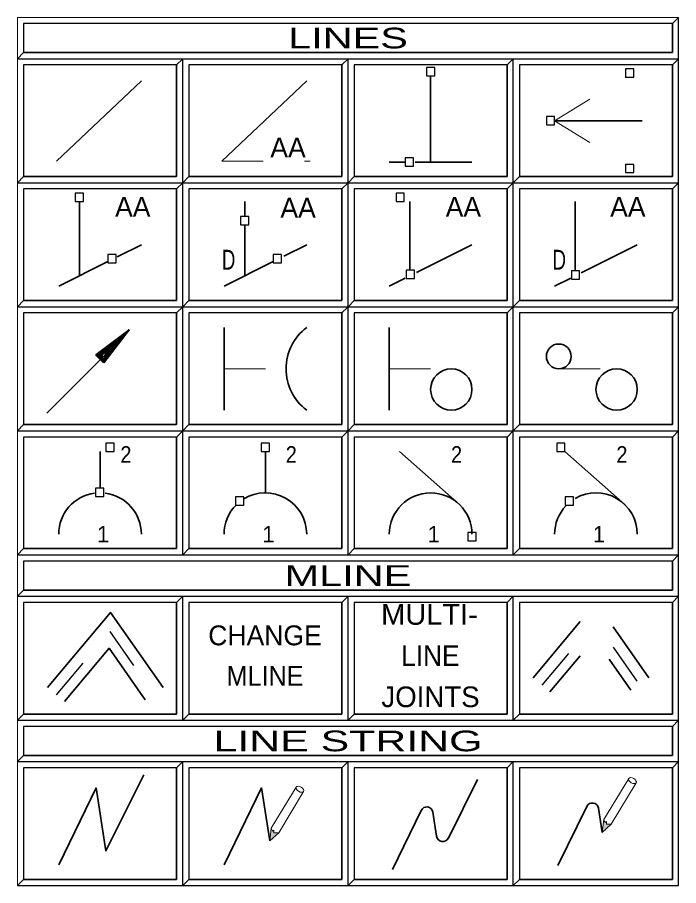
# Model space of a CAD drawing. Extents: x 95906.8 to 95923.6, y 90964.8 to 90972.8.
# Drawn here: x 95908.932 to 95910.532, y 90967.362 to 90969.462 of the extents above; entities that cross this region are included whole.
import ezdxf
from ezdxf.enums import TextEntityAlignment as Align

# ---------------------------------------------------------------- set-up
doc = ezdxf.new("R2010")
doc.units = 0
doc.header["$LTSCALE"] = 0.019
doc.linetypes.add('DOT_DASHED', pattern=[7.7, 5, -1.2, 0.3, -1.2])
doc.linetypes.add('MEDIUM_DASHED', pattern=[4.5, 3, -1.5])
for name, color, linetype, lineweight in [('11', 7, 'Continuous', 25), ('12', 7, 'Continuous', 25), ('17', 7, 'Continuous', 25), ('2', 7, 'Continuous', 13), ('3', 7, 'Continuous', 25), ('6', 7, 'Continuous', 25), ('7', 7, 'Continuous', 35)]:
    doc.layers.add(name, color=color, linetype=linetype, lineweight=lineweight)

msp = doc.modelspace()

# ---------------------------------------------------------------- hatches: boundary and pattern name
at = {"layer": '6'}
for points in [[(95910.3512, 90967.5214), (95910.3474, 90967.4906), (95910.3692, 90967.5106), (95910.3578, 90967.5102), (95910.3578, 90967.5168), (95910.3539, 90967.5142)], [(95909.5466, 90967.5005), (95909.5428, 90967.4697), (95909.5646, 90967.4897), (95909.5532, 90967.4893), (95909.5532, 90967.4959), (95909.5493, 90967.4933)]]:
    msp.add_hatch(color=256, dxfattribs=at).paths.add_polyline_path(points)

# ---------------------------------------------------------------- linework, layer by layer
at = {"layer": '11'}
for points in [[(95909.3473, 90969.0767), (95909.7173, 90969.0767), (95909.7173, 90969.3467), (95909.3473, 90969.3467)], [(95909.7473, 90969.0767), (95910.1173, 90969.0767), (95910.1173, 90969.3467), (95909.7473, 90969.3467)], [(95910.1473, 90969.0767), (95910.5173, 90969.0767), (95910.5173, 90969.3467), (95910.1473, 90969.3467)], [(95908.9473, 90968.7767), (95909.3173, 90968.7767), (95909.3173, 90969.0467), (95908.9473, 90969.0467)], [(95909.3473, 90968.7767), (95909.7173, 90968.7767), (95909.7173, 90969.0467), (95909.3473, 90969.0467)], [(95909.7473, 90968.7767), (95910.1173, 90968.7767), (95910.1173, 90969.0467), (95909.7473, 90969.0467)], [(95910.1473, 90968.7767), (95910.5173, 90968.7767), (95910.5173, 90969.0467), (95910.1473, 90969.0467)], [(95908.9473, 90968.4767), (95909.3173, 90968.4767), (95909.3173, 90968.7467), (95908.9473, 90968.7467)], [(95909.3473, 90968.4767), (95909.7173, 90968.4767), (95909.7173, 90968.7467), (95909.3473, 90968.7467)], [(95909.7473, 90968.4767), (95910.1173, 90968.4767), (95910.1173, 90968.7467), (95909.7473, 90968.7467)], [(95910.1473, 90968.4767), (95910.5173, 90968.4767), (95910.5173, 90968.7467), (95910.1473, 90968.7467)], [(95908.9473, 90968.1767), (95909.3173, 90968.1767), (95909.3173, 90968.4467), (95908.9473, 90968.4467)], [(95909.3473, 90968.1767), (95909.7173, 90968.1767), (95909.7173, 90968.4467), (95909.3473, 90968.4467)], [(95909.7473, 90968.1767), (95910.1173, 90968.1767), (95910.1173, 90968.4467), (95909.7473, 90968.4467)], [(95910.1473, 90968.1767), (95910.5173, 90968.1767), (95910.5173, 90968.4467), (95910.1473, 90968.4467)], [(95908.9473, 90967.7767), (95909.3173, 90967.7767), (95909.3173, 90968.0467), (95908.9473, 90968.0467)], [(95909.3473, 90967.7767), (95909.7173, 90967.7767), (95909.7173, 90968.0467), (95909.3473, 90968.0467)], [(95909.7473, 90967.7767), (95910.1173, 90967.7767), (95910.1173, 90968.0467), (95909.7473, 90968.0467)], [(95910.1473, 90967.7767), (95910.5173, 90967.7767), (95910.5173, 90968.0467), (95910.1473, 90968.0467)], [(95909.3473, 90967.3767), (95909.7173, 90967.3767), (95909.7173, 90967.6467), (95909.3473, 90967.6467)], [(95909.7473, 90967.3767), (95910.1173, 90967.3767), (95910.1173, 90967.6467), (95909.7473, 90967.6467)], [(95910.1473, 90967.3767), (95910.5173, 90967.3767), (95910.5173, 90967.6467), (95910.1473, 90967.6467)]]:
    msp.add_lwpolyline(points, close=True, dxfattribs=at)
at = {"layer": '12'}
for points in [[(95908.9473, 90969.0767), (95909.3173, 90969.0767), (95909.3173, 90969.3467), (95908.9473, 90969.3467)], [(95908.9473, 90967.3767), (95909.3173, 90967.3767), (95909.3173, 90967.6467), (95908.9473, 90967.6467)]]:
    msp.add_lwpolyline(points, close=True, dxfattribs=at)
at = {"layer": '17'}
for points in [[(95908.9473, 90969.3767), (95910.5173, 90969.3767), (95910.5173, 90969.4467), (95908.9473, 90969.4467)], [(95908.9473, 90968.0767), (95910.5173, 90968.0767), (95910.5173, 90968.1467), (95908.9473, 90968.1467)], [(95908.9473, 90967.6767), (95910.5173, 90967.6767), (95910.5173, 90967.7467), (95908.9473, 90967.7467)]]:
    msp.add_lwpolyline(points, close=True, dxfattribs=at)
at = {"layer": '2'}
for points in [[(95908.9323, 90969.4617), (95908.9323, 90969.3617), (95908.9473, 90969.3767), (95908.9473, 90969.4467), (95910.5173, 90969.4467), (95910.5323, 90969.4617)], [(95908.9323, 90969.3617), (95908.9323, 90969.0617), (95908.9473, 90969.0767), (95908.9473, 90969.3467), (95909.3173, 90969.3467), (95909.3323, 90969.3617)], [(95909.3323, 90969.3617), (95909.3323, 90969.0617), (95909.3473, 90969.0767), (95909.3473, 90969.3467), (95909.7173, 90969.3467), (95909.7323, 90969.3617)], [(95909.7323, 90969.3617), (95909.7323, 90969.0617), (95909.7473, 90969.0767), (95909.7473, 90969.3467), (95910.1173, 90969.3467), (95910.1323, 90969.3617)], [(95910.1323, 90969.3617), (95910.1323, 90969.0617), (95910.1473, 90969.0767), (95910.1473, 90969.3467), (95910.5173, 90969.3467), (95910.5323, 90969.3617)], [(95908.9323, 90969.0617), (95908.9323, 90968.7617), (95908.9473, 90968.7767), (95908.9473, 90969.0467), (95909.3173, 90969.0467), (95909.3323, 90969.0617)], [(95909.3323, 90969.0617), (95909.3323, 90968.7617), (95909.3473, 90968.7767), (95909.3473, 90969.0467), (95909.7173, 90969.0467), (95909.7323, 90969.0617)], [(95909.7323, 90969.0617), (95909.7323, 90968.7617), (95909.7473, 90968.7767), (95909.7473, 90969.0467), (95910.1173, 90969.0467), (95910.1323, 90969.0617)], [(95910.1323, 90969.0617), (95910.1323, 90968.7617), (95910.1473, 90968.7767), (95910.1473, 90969.0467), (95910.5173, 90969.0467), (95910.5323, 90969.0617)], [(95908.9323, 90968.7617), (95908.9323, 90968.4617), (95908.9473, 90968.4767), (95908.9473, 90968.7467), (95909.3173, 90968.7467), (95909.3323, 90968.7617)], [(95909.3323, 90968.7617), (95909.3323, 90968.4617), (95909.3473, 90968.4767), (95909.3473, 90968.7467), (95909.7173, 90968.7467), (95909.7323, 90968.7617)], [(95909.7323, 90968.7617), (95909.7323, 90968.4617), (95909.7473, 90968.4767), (95909.7473, 90968.7467), (95910.1173, 90968.7467), (95910.1323, 90968.7617)], [(95910.1323, 90968.7617), (95910.1323, 90968.4617), (95910.1473, 90968.4767), (95910.1473, 90968.7467), (95910.5173, 90968.7467), (95910.5323, 90968.7617)], [(95908.9323, 90968.4617), (95908.9323, 90968.1617), (95908.9473, 90968.1767), (95908.9473, 90968.4467), (95909.3173, 90968.4467), (95909.3323, 90968.4617)], [(95909.3323, 90968.4617), (95909.3323, 90968.1617), (95909.3473, 90968.1767), (95909.3473, 90968.4467), (95909.7173, 90968.4467), (95909.7323, 90968.4617)], [(95909.7323, 90968.4617), (95909.7323, 90968.1617), (95909.7473, 90968.1767), (95909.7473, 90968.4467), (95910.1173, 90968.4467), (95910.1323, 90968.4617)], [(95910.1323, 90968.4617), (95910.1323, 90968.1617), (95910.1473, 90968.1767), (95910.1473, 90968.4467), (95910.5173, 90968.4467), (95910.5323, 90968.4617)], [(95908.9323, 90968.1617), (95908.9323, 90968.0617), (95908.9473, 90968.0767), (95908.9473, 90968.1467), (95910.5173, 90968.1467), (95910.5323, 90968.1617)], [(95908.9323, 90968.0617), (95908.9323, 90967.7617), (95908.9473, 90967.7767), (95908.9473, 90968.0467), (95909.3173, 90968.0467), (95909.3323, 90968.0617)], [(95909.3323, 90968.0617), (95909.3323, 90967.7617), (95909.3473, 90967.7767), (95909.3473, 90968.0467), (95909.7173, 90968.0467), (95909.7323, 90968.0617)], [(95909.7323, 90968.0617), (95909.7323, 90967.7617), (95909.7473, 90967.7767), (95909.7473, 90968.0467), (95910.1173, 90968.0467), (95910.1323, 90968.0617)], [(95910.1323, 90968.0617), (95910.1323, 90967.7617), (95910.1473, 90967.7767), (95910.1473, 90968.0467), (95910.5173, 90968.0467), (95910.5323, 90968.0617)], [(95908.9323, 90967.7617), (95908.9323, 90967.6617), (95908.9473, 90967.6767), (95908.9473, 90967.7467), (95910.5173, 90967.7467), (95910.5323, 90967.7617)], [(95908.9323, 90967.6617), (95908.9323, 90967.3617), (95908.9473, 90967.3767), (95908.9473, 90967.6467), (95909.3173, 90967.6467), (95909.3323, 90967.6617)], [(95909.3323, 90967.6617), (95909.3323, 90967.3617), (95909.3473, 90967.3767), (95909.3473, 90967.6467), (95909.7173, 90967.6467), (95909.7323, 90967.6617)], [(95909.7323, 90967.6617), (95909.7323, 90967.3617), (95909.7473, 90967.3767), (95909.7473, 90967.6467), (95910.1173, 90967.6467), (95910.1323, 90967.6617)], [(95910.1323, 90967.6617), (95910.1323, 90967.3617), (95910.1473, 90967.3767), (95910.1473, 90967.6467), (95910.5173, 90967.6467), (95910.5323, 90967.6617)]]:
    msp.add_lwpolyline(points, close=True, dxfattribs=at)
at = {"layer": '3'}
for points in [[(95908.9323, 90969.3617), (95910.5323, 90969.3617), (95910.5323, 90969.4617), (95910.5173, 90969.4467), (95910.5173, 90969.3767), (95908.9473, 90969.3767)], [(95908.9323, 90969.0617), (95909.3323, 90969.0617), (95909.3323, 90969.3617), (95909.3173, 90969.3467), (95909.3173, 90969.0767), (95908.9473, 90969.0767)], [(95909.3323, 90969.0617), (95909.7323, 90969.0617), (95909.7323, 90969.3617), (95909.7173, 90969.3467), (95909.7173, 90969.0767), (95909.3473, 90969.0767)], [(95909.7323, 90969.0617), (95910.1323, 90969.0617), (95910.1323, 90969.3617), (95910.1173, 90969.3467), (95910.1173, 90969.0767), (95909.7473, 90969.0767)], [(95910.1323, 90969.0617), (95910.5323, 90969.0617), (95910.5323, 90969.3617), (95910.5173, 90969.3467), (95910.5173, 90969.0767), (95910.1473, 90969.0767)], [(95908.9323, 90968.7617), (95909.3323, 90968.7617), (95909.3323, 90969.0617), (95909.3173, 90969.0467), (95909.3173, 90968.7767), (95908.9473, 90968.7767)], [(95909.3323, 90968.7617), (95909.7323, 90968.7617), (95909.7323, 90969.0617), (95909.7173, 90969.0467), (95909.7173, 90968.7767), (95909.3473, 90968.7767)], [(95909.7323, 90968.7617), (95910.1323, 90968.7617), (95910.1323, 90969.0617), (95910.1173, 90969.0467), (95910.1173, 90968.7767), (95909.7473, 90968.7767)], [(95910.1323, 90968.7617), (95910.5323, 90968.7617), (95910.5323, 90969.0617), (95910.5173, 90969.0467), (95910.5173, 90968.7767), (95910.1473, 90968.7767)], [(95908.9323, 90968.4617), (95909.3323, 90968.4617), (95909.3323, 90968.7617), (95909.3173, 90968.7467), (95909.3173, 90968.4767), (95908.9473, 90968.4767)], [(95909.3323, 90968.4617), (95909.7323, 90968.4617), (95909.7323, 90968.7617), (95909.7173, 90968.7467), (95909.7173, 90968.4767), (95909.3473, 90968.4767)], [(95909.7323, 90968.4617), (95910.1323, 90968.4617), (95910.1323, 90968.7617), (95910.1173, 90968.7467), (95910.1173, 90968.4767), (95909.7473, 90968.4767)], [(95910.1323, 90968.4617), (95910.5323, 90968.4617), (95910.5323, 90968.7617), (95910.5173, 90968.7467), (95910.5173, 90968.4767), (95910.1473, 90968.4767)], [(95908.9323, 90968.1617), (95909.3323, 90968.1617), (95909.3323, 90968.4617), (95909.3173, 90968.4467), (95909.3173, 90968.1767), (95908.9473, 90968.1767)], [(95909.3323, 90968.1617), (95909.7323, 90968.1617), (95909.7323, 90968.4617), (95909.7173, 90968.4467), (95909.7173, 90968.1767), (95909.3473, 90968.1767)], [(95909.7323, 90968.1617), (95910.1323, 90968.1617), (95910.1323, 90968.4617), (95910.1173, 90968.4467), (95910.1173, 90968.1767), (95909.7473, 90968.1767)], [(95910.1323, 90968.1617), (95910.5323, 90968.1617), (95910.5323, 90968.4617), (95910.5173, 90968.4467), (95910.5173, 90968.1767), (95910.1473, 90968.1767)], [(95908.9323, 90968.0617), (95910.5323, 90968.0617), (95910.5323, 90968.1617), (95910.5173, 90968.1467), (95910.5173, 90968.0767), (95908.9473, 90968.0767)], [(95908.9323, 90967.7617), (95909.3323, 90967.7617), (95909.3323, 90968.0617), (95909.3173, 90968.0467), (95909.3173, 90967.7767), (95908.9473, 90967.7767)], [(95909.3323, 90967.7617), (95909.7323, 90967.7617), (95909.7323, 90968.0617), (95909.7173, 90968.0467), (95909.7173, 90967.7767), (95909.3473, 90967.7767)], [(95909.7323, 90967.7617), (95910.1323, 90967.7617), (95910.1323, 90968.0617), (95910.1173, 90968.0467), (95910.1173, 90967.7767), (95909.7473, 90967.7767)], [(95910.1323, 90967.7617), (95910.5323, 90967.7617), (95910.5323, 90968.0617), (95910.5173, 90968.0467), (95910.5173, 90967.7767), (95910.1473, 90967.7767)], [(95908.9323, 90967.6617), (95910.5323, 90967.6617), (95910.5323, 90967.7617), (95910.5173, 90967.7467), (95910.5173, 90967.6767), (95908.9473, 90967.6767)], [(95908.9323, 90967.3617), (95909.3323, 90967.3617), (95909.3323, 90967.6617), (95909.3173, 90967.6467), (95909.3173, 90967.3767), (95908.9473, 90967.3767)], [(95909.3323, 90967.3617), (95909.7323, 90967.3617), (95909.7323, 90967.6617), (95909.7173, 90967.6467), (95909.7173, 90967.3767), (95909.3473, 90967.3767)], [(95909.7323, 90967.3617), (95910.1323, 90967.3617), (95910.1323, 90967.6617), (95910.1173, 90967.6467), (95910.1173, 90967.3767), (95909.7473, 90967.3767)], [(95910.1323, 90967.3617), (95910.5323, 90967.3617), (95910.5323, 90967.6617), (95910.5173, 90967.6467), (95910.5173, 90967.3767), (95910.1473, 90967.3767)]]:
    msp.add_lwpolyline(points, close=True, dxfattribs=at)
at = {"layer": '6', "lineweight": 35}
for p, q in [((95909.9323, 90969.1117), (95909.9323, 90969.3202)), ((95909.0267, 90969.1142), (95909.2327, 90969.308)), ((95909.4267, 90969.1142), (95909.6327, 90969.308)), ((95910.2323, 90969.2117), (95910.4444, 90969.2117)), ((95909.8323, 90969.1117), (95909.8687, 90969.1117)), ((95910.0323, 90969.1117), (95909.895, 90969.1117)), ((95909.0823, 90968.8367), (95909.0823, 90969.0167)), ((95909.4823, 90969.0167), (95909.4823, 90968.9828)), ((95909.8823, 90969.0167), (95909.8823, 90968.8511)), ((95910.2823, 90969.0167), (95910.2823, 90968.8511)), ((95909.4823, 90968.8367), (95909.4823, 90968.9583)), ((95909.2323, 90968.9117), (95909.1737, 90968.8824)), ((95909.6323, 90968.9117), (95909.5772, 90968.8842)), ((95910.0323, 90968.9117), (95909.8983, 90968.8447)), ((95910.4323, 90968.9117), (95910.2966, 90968.8438)), ((95909.0323, 90968.8117), (95909.1511, 90968.8711)), ((95909.4323, 90968.8117), (95909.5509, 90968.871)), ((95909.8323, 90968.8117), (95909.8705, 90968.8308)), ((95910.2323, 90968.8117), (95910.2711, 90968.8311)), ((95909.4323, 90968.7117), (95909.4323, 90968.5117)), ((95909.8323, 90968.7117), (95909.8323, 90968.5117)), ((95909.1323, 90968.4117), (95909.1323, 90968.3255)), ((95909.5323, 90968.3117), (95909.5323, 90968.4117)), ((95910.003, 90968.2824), (95909.8573, 90968.4117)), ((95910.403, 90968.2824), (95910.2573, 90968.4117)), ((95910.1804, 90967.8646), (95910.2942, 90968.0003)), ((95910.3737, 90967.9877), (95910.4599, 90967.8646)), ((95910.221, 90967.8306), (95910.2942, 90967.9179)), ((95910.3638, 90967.9095), (95910.4165, 90967.8342)), ((95909.9751, 90967.4766), (95910.0458, 90967.6182)), ((95910.2404, 90967.41), (95910.3101, 90967.5533)), ((95910.3384, 90967.549), (95910.3474, 90967.4906)), ((95909.8398, 90967.4004), (95909.9095, 90967.5437)), ((95909.9378, 90967.5394), (95909.9468, 90967.481))]:
    msp.add_line(p, q, dxfattribs=at)
at = {"layer": '6', "linetype": 'MEDIUM_DASHED', "lineweight": 13}
for p, q in [((95910.2323, 90969.2117), (95910.404, 90969.3173)), ((95910.2323, 90969.2117), (95910.404, 90969.1061)), ((95909.4267, 90969.1142), (95909.6406, 90969.1142)), ((95909.4323, 90968.6117), (95909.5823, 90968.6117)), ((95909.8323, 90968.6117), (95909.9823, 90968.6117)), ((95910.2423, 90968.6117), (95910.3823, 90968.6117))]:
    msp.add_line(p, q, dxfattribs=at)
at = {"layer": '6', "lineweight": 40}
for p, q in [((95909.2027, 90968.7063), (95909.1219, 90968.6457)), ((95909.2027, 90968.7063), (95909.1418, 90968.6258)), ((95909.1882, 90968.6918), (95909.1262, 90968.6454)), ((95909.1882, 90968.6918), (95909.1415, 90968.6303)), ((95909.1735, 90968.6772), (95909.1307, 90968.6451)), ((95909.1589, 90968.6627), (95909.1351, 90968.6448)), ((95909.1589, 90968.6627), (95909.1409, 90968.639)), ((95909.1735, 90968.6772), (95909.1412, 90968.6346)), ((95909.1418, 90968.6258), (95909.1219, 90968.6457)), ((95909.1415, 90968.6303), (95909.1262, 90968.6454)), ((95909.1412, 90968.6346), (95909.1307, 90968.6451)), ((95909.1409, 90968.639), (95909.1351, 90968.6448))]:
    msp.add_line(p, q, dxfattribs=at)
at = {"layer": '6'}
msp.add_line((95909.1616, 90968.6625), (95909.0036, 90968.5045), dxfattribs=at)
at = {"layer": '6', "linetype": 'DOT_DASHED'}
for p, q in [((95910.2022, 90967.8463), (95910.2942, 90967.956)), ((95910.3737, 90967.9381), (95910.4366, 90967.8483))]:
    msp.add_line(p, q, dxfattribs=at)
at = {"layer": '6', "lineweight": 13}
for p, q in [((95910.3512, 90967.5214), (95910.4115, 90967.6211)), ((95909.5466, 90967.5005), (95909.6069, 90967.6002)), ((95910.3692, 90967.5106), (95910.4295, 90967.6103)), ((95909.5646, 90967.4897), (95909.6249, 90967.5894))]:
    msp.add_line(p, q, dxfattribs=at)
at = {"layer": '6'}
for points in [[(95909.9223, 90969.3202), (95909.9423, 90969.3202), (95909.9423, 90969.3402), (95909.9223, 90969.3402)], [(95910.404, 90969.3173), (95910.424, 90969.3173), (95910.424, 90969.3373), (95910.404, 90969.3373)], [(95910.2123, 90969.2017), (95910.2323, 90969.2017), (95910.2323, 90969.2217), (95910.2123, 90969.2217)], [(95909.8706, 90969.1019), (95909.8906, 90969.1019), (95909.8906, 90969.1219), (95909.8706, 90969.1219)], [(95910.404, 90969.0861), (95910.424, 90969.0861), (95910.424, 90969.1061), (95910.404, 90969.1061)], [(95909.0723, 90969.0167), (95909.0923, 90969.0167), (95909.0923, 90969.0367), (95909.0723, 90969.0367)], [(95909.8486, 90969.0167), (95909.8686, 90969.0167), (95909.8686, 90969.0367), (95909.8486, 90969.0367)], [(95909.472, 90968.9602), (95909.492, 90968.9602), (95909.492, 90968.9802), (95909.472, 90968.9802)], [(95909.1513, 90968.868), (95909.1713, 90968.868), (95909.1713, 90968.888), (95909.1513, 90968.888)], [(95909.5513, 90968.868), (95909.5713, 90968.868), (95909.5713, 90968.888), (95909.5513, 90968.888)], [(95909.8731, 90968.8304), (95909.8931, 90968.8304), (95909.8931, 90968.8504), (95909.8731, 90968.8504)], [(95910.2727, 90968.8285), (95910.2927, 90968.8285), (95910.2927, 90968.8485), (95910.2727, 90968.8485)], [(95909.1463, 90968.4117), (95909.1663, 90968.4117), (95909.1663, 90968.4317), (95909.1463, 90968.4317)], [(95909.5223, 90968.4117), (95909.5423, 90968.4117), (95909.5423, 90968.4317), (95909.5223, 90968.4317)], [(95910.2373, 90968.4117), (95910.2573, 90968.4117), (95910.2573, 90968.4317), (95910.2373, 90968.4317)], [(95909.1213, 90968.3029), (95909.1413, 90968.3029), (95909.1413, 90968.3229), (95909.1213, 90968.3229)], [(95909.4602, 90968.2822), (95909.4802, 90968.2822), (95909.4802, 90968.3022), (95909.4602, 90968.3022)], [(95910.2581, 90968.2822), (95910.2781, 90968.2822), (95910.2781, 90968.3022), (95910.2581, 90968.3022)], [(95910.0226, 90968.1956), (95910.0426, 90968.1956), (95910.0426, 90968.2156), (95910.0226, 90968.2156)]]:
    msp.add_lwpolyline(points, close=True, dxfattribs=at)
at = {"layer": '6', "lineweight": 35}
for points in [[(95909.0056, 90967.8411), (95909.1579, 90968.0227), (95909.2851, 90967.8411)], [(95909.0462, 90967.8071), (95909.1541, 90967.9358), (95909.2417, 90967.8107)], [(95909.0323, 90967.4117), (95909.1229, 90967.598), (95909.1465, 90967.4458), (95909.2383, 90967.6295)], [(95909.4323, 90967.4117), (95909.5229, 90967.598), (95909.5428, 90967.4697)]]:
    msp.add_lwpolyline(points, dxfattribs=at)
at = {"layer": '6', "linetype": 'DOT_DASHED'}
msp.add_lwpolyline([(95909.0274, 90967.8228), (95909.1559, 90967.976), (95909.2618, 90967.8248)], dxfattribs=at)
at = {"layer": '6', "lineweight": 13}
for points in [[(95910.3512, 90967.5214), (95910.3474, 90967.4906), (95910.3692, 90967.5106), (95910.3578, 90967.5102), (95910.3578, 90967.5168), (95910.3539, 90967.5142)], [(95909.5466, 90967.5005), (95909.5428, 90967.4697), (95909.5646, 90967.4897), (95909.5532, 90967.4893), (95909.5532, 90967.4959), (95909.5493, 90967.4933)]]:
    msp.add_lwpolyline(points, close=True, dxfattribs=at)
at = {"layer": '6', "lineweight": 35}
for centre, radius in [((95910.2423, 90968.6417), 0.03), ((95909.9823, 90968.5617), 0.05), ((95910.3823, 90968.5617), 0.05)]:
    msp.add_circle(centre, radius, dxfattribs=at)
for centre, radius, start, end in [((95909.7073, 90968.6117), 0.125, 126.8699, 233.1301), ((95909.1323, 90968.2117), 0.1, 97.558, 180), ((95909.1323, 90968.2117), 0.1, 0, 82.9369), ((95909.5323, 90968.2117), 0.1, 0, 121.3266), ((95909.9323, 90968.2117), 0.1, 0, 180), ((95910.3323, 90968.2117), 0.1, 0, 119.9911), ((95909.5323, 90968.2117), 0.1, 135.1578, 180), ((95910.3323, 90968.2117), 0.1, 136.7381, 180), ((95909.9229, 90967.5371), 0.015, 8.8599, 154.0466), ((95910.3236, 90967.5467), 0.015, 8.8599, 154.0466), ((95909.9616, 90967.4833), 0.015, 188.7687, 333.435)]:
    msp.add_arc(centre, radius, start, end, dxfattribs=at)
at = {"layer": '6', "lineweight": 13}
for centre in [(95910.4205, 90967.6157), (95909.6159, 90967.5948)]:
    msp.add_ellipse(centre, major_axis=(-0.009, 0.0054), ratio=0.555562, dxfattribs=at)

# ---------------------------------------------------------------- texts
at = {"layer": '6'}
for s, height, p in [('AA', 0.048, (95909.5872, 90969.1229)), ('AA', 0.048, (95909.2116, 90968.9795)), ('AA', 0.048, (95909.6116, 90968.9773)), ('AA', 0.048, (95910.0115, 90968.9794)), ('AA', 0.048, (95910.4094, 90968.9795)), ('1', 0.04, (95909.1398, 90968.1917)), ('1', 0.04, (95909.5398, 90968.1917)), ('1', 0.04, (95909.9398, 90968.1917)), ('1', 0.04, (95910.3398, 90968.1917)), ('CHANGE', 0.048, (95909.5315, 90967.943)), ('JOINTS', 0.04999, (95909.9319, 90967.7934))]:
    msp.add_text(s, height=height, dxfattribs=at).set_placement(p, align=Align.CENTER)
for s, height, width, p in [('D', 0.048, 0.7, (95909.4435, 90968.8515)), ('D', 0.048, 0.7, (95910.2435, 90968.8515)), ('2', 0.04, 0.9, (95909.195, 90968.3846)), ('2', 0.04, 0.9, (95909.5951, 90968.3846)), ('2', 0.04, 0.9, (95909.995, 90968.3846)), ('2', 0.04, 0.9, (95910.3951, 90968.3846)), ('MULTI-', 0.04999, 1.05, (95909.9294, 90967.9926)), ('LINE', 0.04999, 0.95, (95909.9315, 90967.893)), ('MLINE', 0.048, 0.95, (95909.5315, 90967.845))]:
    msp.add_text(s, height=height, dxfattribs=dict(at, width=width)).set_placement(p, align=Align.CENTER)
at = {"layer": '7'}
for s, width, p in [('         LINES         ', 1.5, (95909.7323, 90969.3867)), ('         MLINE         ', 1.5, (95909.7322, 90968.0867)), ('      LINE STRING      ', 1.55, (95909.7322, 90967.6867))]:
    msp.add_text(s, height=0.04999, dxfattribs=dict(at, width=width)).set_placement(p, align=Align.CENTER)

doc.saveas('drawing.dxf')
